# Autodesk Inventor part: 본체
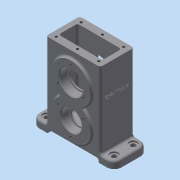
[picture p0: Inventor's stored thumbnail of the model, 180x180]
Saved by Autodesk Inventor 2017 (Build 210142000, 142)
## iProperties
Created: 2020-03
Part Number: 본체
Material: 알루미늄 6061
Document SubType Name: Modeling
Designer: mduedu
Density: 2.71 g/cm^3
Appearance: 기본값
Mass: 597.031 g
Surface Area: 576.062 cm^2
Volume: 220.307 cm^3
Author: mduedu
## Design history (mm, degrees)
sketch "스케치1"
  geometry: L1 (-56, 0)-(56, 0); L2 (56, 0)-(56, 10); L3 (-56, 10)-(-56, 0); L4 (37, 10)-(37, 114); L5 (37, 114)-(-37, 114); L6 (-37, 114)-(-37, 10); L7 (56, 10)-(37, 10); L8 (-37, 10)-(-56, 10); L9 (0, 0)-(0, 114); 1 further point
  constraints: 18 end point, 5 parallel, 2 midpoint, 2 vertical, 1 coincident, 1 horizontal, 1 perpendicular
  dimensions: "d0" = 112 distance of L1.start L1.end; "d2" = 10 distance of L1.end L2.end; "d3" = 114 distance between parallel lines of L5 L1; "d4" = 74 distance between parallel lines of L4 L6
extrude "돌출1" new body sketch "스케치1" stored distance "d5" = 46; taper "d6" = 0 deg
sketch "스케치2"
  geometry: L1 (56, 0)-(-56, 0) reference; C1 r 26 at (0, 34); C2 r 26 at (0, 79); 1 further point
  constraints: 2 centre point, 2 vertical alignment, 1 equal radius
  dimensions: "d7" = 52 diameter of C2; "d9" = 34 distance from line of C1.centre L1; "d10" = 45 distance of C2.centre C1.centre
extrude "돌출2" join sketch "스케치2" stored distance "d11" = 52; taper "d12" = 0 deg
fillet "모깎기1" dims "d13" = 3
fillet "모깎기2" dims "d14" = 3
fillet "모깎기3" dims "d15" = 10
fillet "모깎기4" dims "d16" = 3
fillet "모깎기5" dims "d17" = 3
sketch "스케치3"
  geometry: L1 (-30, 114)-(30, 114); L2 (30, 114)-(30, 13); L3 (30, 13)-(-30, 13); L4 (-30, 13)-(-30, 114); L5 (-34, 114)-(34, 114) reference; L6 (46, 0)-(-46, 0) reference; 2 further points
  constraints: 8 end point, 2 parallel, 1 collinear, 1 horizontal, 1 midpoint, 1 perpendicular, 1 vertical alignment
  dimensions: "d18" = 60 distance between parallel lines of L2 L4; "d20" = 13 distance between parallel lines of L3 L6
extrude "돌출3" cut sketch "스케치3" stored distance "d21" = 26; taper "d22" = 0 deg
fillet "모깎기6" dims "d23" = 3
fillet "모깎기7" dims "d24" = 3
sketch "스케치4"
  geometry: L1 (-35, 0)-(35, 0); L2 (35, 0)-(35, 5); L3 (35, 5)-(-35, 5); L4 (-35, 5)-(-35, 0); 2 further points
  constraints: 8 end point, 2 parallel, 1 coincident, 1 horizontal, 1 midpoint, 1 perpendicular
  dimensions: "d25" = 70 distance of L1.start L1.end; "d27" = 5 distance of L1.end L2.end
extrude "돌출4" cut sketch "스케치4" stored distance "d28" = 26; taper "d29" = 0 deg
fillet "모깎기8" dims "d30" = 3
sketch "스케치5"
  geometry: A1 r 10 centre (-86, 33) between (-86, 43) and (-96, 33) reference; A2 r 10 centre (-86, 7) between (-96, 7) and (-86, -3) reference; A3 r 10 centre (6, 7) between (6, -3) and (16, 7) reference; A4 r 10 centre (6, 33) between (16, 33) and (6, 43) reference; 5 further points
  constraints: 4 coincident
hole "구멍1" sketch "스케치5" at (-86, 33), (-86, 7), (6, 7), (6, 33) diameter "d31" = 6.6; stored, may be unused: countersink angle "d35" = 90 deg, drill point angle "d37" = 118 deg; dims "d32" = 6, "d33" = 11, "d34" = 2, "d36" = 8
sketch "스케치6"
  geometry: A1 r 26 centre (0, 34) between (-16.403, 54.172) and (16.403, 54.172) reference; A2 r 3 centre (18.296, 56.5) between (16.403, 58.828) and (16.403, 54.172) reference; A3 r 26 centre (0, 79) between (16.403, 58.828) and (-16.403, 58.828) reference; A4 r 3 centre (-18.296, 56.5) between (-16.403, 54.172) and (-16.403, 58.828) reference; 2 further points
  constraints: 1 coincident
hole "구멍2" sketch "스케치6" at (0, 79) diameter "d38" = 28; stored, may be unused: countersink angle "d42" = 90 deg, drill point angle "d44" = 118 deg; dims "d39" = 6, "d40" = 32, "d41" = 11, "d43" = 8
sketch "스케치7"
  geometry: C1 r 16 at (0, 79) reference; A1 r 26 centre (0, 34) between (-16.403, 54.172) and (16.403, 54.172) reference; A2 r 3 centre (18.296, 56.5) between (16.403, 58.828) and (16.403, 54.172) reference; A3 r 26 centre (0, 79) between (16.403, 58.828) and (-16.403, 58.828) reference; A4 r 3 centre (-18.296, 56.5) between (-16.403, 54.172) and (-16.403, 58.828) reference; 2 further points
  constraints: 1 coincident
hole "구멍3" sketch "스케치7" at (0, 34) diameter "d45" = 24; stored, may be unused: countersink angle "d49" = 90 deg, drill point angle "d51" = 118 deg; dims "d46" = 6, "d47" = 28, "d48" = 11, "d50" = 8
sketch "스케치8"
  geometry: C1 r 14 at (0, 34) reference; A1 r 26 centre (0, 34) between (-16.403, 54.172) and (16.403, 54.172) reference; A2 r 3 centre (18.296, 56.5) between (16.403, 58.828) and (16.403, 54.172) reference; A3 r 26 centre (0, 79) between (16.403, 58.828) and (-16.403, 58.828) reference; A4 r 3 centre (-18.296, 56.5) between (-16.403, 54.172) and (-16.403, 58.828) reference; 2 further points
  constraints: 1 coincident
hole "구멍4" sketch "스케치8" at (0, 79) diameter "d52" = 24; stored, may be unused: countersink angle "d56" = 90 deg, drill point angle "d58" = 118 deg; dims "d53" = 6, "d54" = 28, "d55" = 11, "d57" = 8
sketch "스케치9" dims "d59" = 40
  geometry: C1 r 14 at (0, 34) reference; C2 r 16 at (0, 79) reference; A1 r 26 centre (0, 34) between (-16.403, 54.172) and (16.403, 54.172) reference; A2 r 3 centre (18.296, 56.5) between (16.403, 58.828) and (16.403, 54.172) reference; A3 r 26 centre (0, 79) between (16.403, 58.828) and (-16.403, 58.828) reference; A4 r 3 centre (-18.296, 56.5) between (-16.403, 54.172) and (-16.403, 58.828) reference; 3 further points
  constraints: 2 vertical alignment, 1 coincident, 2 other
hole "구멍5" sketch "스케치9" at (0, 99) diameter "d61" = 3.242; stored, may be unused: countersink angle "d65" = 90 deg, drill point angle "d67" = 118 deg; dims "d62" = 8, "d63" = 28, "d64" = 11, "d66" = 10
sketch "스케치10" dims "d71" = 40
  geometry: C1 r 1.621 at (17.321, 69) reference; C2 r 1.621 at (-17.321, 69) reference; C3 r 1.621 at (0, 99) reference; C4 r 14 at (0, 34) reference; C5 r 16 at (0, 79) reference; A1 r 26 centre (0, 34) between (-16.403, 54.172) and (16.403, 54.172) reference; A2 r 3 centre (18.296, 56.5) between (16.403, 58.828) and (16.403, 54.172) reference; A3 r 26 centre (0, 79) between (16.403, 58.828) and (-16.403, 58.828) reference; A4 r 3 centre (-18.296, 56.5) between (-16.403, 54.172) and (-16.403, 58.828) reference; 3 further points
  constraints: 2 vertical alignment, 1 coincident, 2 other
hole "구멍6" sketch "스케치10" at (0, 14) diameter "d72" = 3.242; stored, may be unused: countersink angle "d76" = 90 deg, drill point angle "d78" = 118 deg; dims "d73" = 8, "d74" = 28, "d75" = 11, "d77" = 10
sketch "스케치11"
  geometry: L1 (5, 6)-(63, 6); L2 (63, 6)-(63, 40); L3 (63, 40)-(5, 40); L4 (5, 40)-(5, 6); L5 (5, 6)-(63, 40); L6 (63, 6)-(5, 40); 7 further points
  constraints: 12 end point, 4 coincident, 4 midpoint, 2 parallel, 1 horizontal, 1 perpendicular
  dimensions: "d82" = 58 distance of L3.end L2.end; "d83" = 34 distance of L2.end L1.end
hole "구멍7" sketch "스케치11" at (5, 40), (63, 40), (63, 6), (5, 6), (34, 6), (34, 40) diameter "d84" = 3.242; stored, may be unused: countersink angle "d88" = 90 deg, drill point angle "d90" = 118 deg; dims "d85" = 8, "d86" = 28, "d87" = 11, "d89" = 10
fillet "모깎기9" dims "d91" = 0.3
chamfer "모따기1" distance "d92" = 1; stored, may be unused: second distance "d93" = 2, angle "d94" = 45 deg
sketch "스케치12"
  geometry: 2 further points
  constraints: 1 coincident
hole "구멍8" sketch "스케치12" at (0, -23) diameter "d95" = 4.917; stored, may be unused: countersink angle "d99" = 90 deg, drill point angle "d101" = 118 deg; dims "d96" = 8, "d97" = 12, "d98" = 1, "d100" = 10
sketch "스케치13"
  geometry: L1 (33, -13)-(7, -13) reference; L2 (40, 101)-(0, 101) reference; 3 further points
  constraints: 1 midpoint, 1 vertical alignment, 1 other
  dimensions: "d102" = 40 distance from line of point (20, 61) L2
feature "엠보싱1" sketch "스케치13" dims "d0" = 112, "d2" = 10, "d3" = 114, "d4" = 74, "d13" = 3, "d103" = 0.5, "d104" = 0
node "솔리드1"
mirror "대칭1"
pattern_circular "원형 패턴1" dims angle "d69" = 360 deg
pattern_circular "원형 패턴2" dims angle "d80" = 360 deg
mirror "대칭2"
node "투영된 루프1"
node "투영된 루프2"
node "투영된 루프3"
node "투영된 루프4"
node "투영된 루프5"
